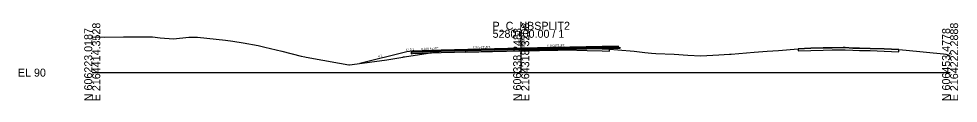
# Model space of a CAD drawing. Extents: x -26 to 1303, y -10 to 12038.
# Drawn here: x -25.7 to 302.8, y 490.3 to 517.8 of the extents above; entities that cross this region are included whole.
import ezdxf

# ---------------------------------------------------------------- set-up
doc = ezdxf.new("R2010")
doc.units = 0
for name, color, linetype in [('RD_GPK_XS_Cell', 7, 'Continuous'), ('RD_XS_Base', 7, 'Continuous'), ('RD_XS_ExGround', 7, 'Continuous'), ('RD_XS_ExPaveRet', 7, 'Continuous'), ('RD_XS_Greenside', 7, 'Continuous'), ('RD_XS_Pave', 7, 'Continuous'), ('RD_XS_PaveOvlay_CP', 7, 'Continuous'), ('RD_XS_TieSlope', 7, 'Continuous'), ('RD_XS_TX_Elev_EX', 7, 'Continuous'), ('RD_XS_TX_Elev_PR', 7, 'Continuous'), ('RD_XS_TX_ShdSlope', 7, 'Continuous'), ('RD_XS_TX_Slope', 7, 'Continuous')]:
    doc.layers.add(name, color=color, linetype=linetype)

msp = doc.modelspace()

# ---------------------------------------------------------------- linework, layer by layer
at = {"layer": 'RD_GPK_XS_Cell'}
for p, q in [((150, 500), (150, 515)), ((0, 500), (150, 500)), ((150, 500), (300, 500))]:
    msp.add_line(p, q, dxfattribs=at)
at = {"layer": 'RD_XS_Base'}
for p, q in [((112, 507.15), (111.5, 507.13)), ((111.5, 507.13), (111.5, 507.13)), ((111.5, 507.13), (111.5, 506.63)), ((111.5, 506.63), (112, 506.65)), ((122, 507.55), (112, 507.15)), ((112, 507.15), (112, 507.15)), ((112, 506.65), (122, 507.05)), ((112, 506.65), (112, 506.65)), ((150, 508.25), (122, 507.55)), ((122, 507.05), (150, 507.75)), ((122, 507.55), (122, 507.55)), ((122, 507.05), (122, 507.05)), ((150, 508.25), (184, 508.93)), ((184.5, 508.44), (150, 507.75)), ((150, 507.75), (150, 508.41)), ((150, 508.41), (150, 508.41)), ((150, 508.41), (150, 508.41)), ((150, 508.41), (150, 508.25)), ((150, 508.25), (150, 508.25)), ((150, 507.75), (150, 508.25)), ((150, 508.25), (150, 508.25)), ((150, 508.25), (150, 508.25)), ((150, 507.75), (150, 507.75)), ((174, 508.73), (174, 508.73)), ((174, 508.73), (174, 508.73)), ((174, 508.23), (174, 508.23)), ((174, 508.23), (174, 508.23)), ((184, 508.93), (184, 508.93)), ((184.5, 508.94), (184.5, 508.44)), ((184.5, 508.91), (184.5, 508.91))]:
    msp.add_line(p, q, dxfattribs=at)
at = {"layer": 'RD_XS_ExGround'}
msp.add_lwpolyline([(0, 512.4), (2.15, 512.52), (4.13, 512.42), (10.93, 512.5), (11.47, 512.49), (13.95, 512.5), (20.44, 512.53), (21.09, 512.53), (23.73, 512.19), (28.47, 511.89), (33.78, 512.45), (36.86, 512.46), (46.57, 511.31), (49.22, 510.96), (52.81, 510.38), (58.06, 509.52), (60.31, 508.95), (66.35, 507.5), (73.05, 505.81), (74.33, 505.49), (74.82, 505.39), (86.47, 503.34), (89.77, 502.77), (90.02, 502.7), (90.87, 502.83), (103.02, 504.5), (108.63, 505.44), (108.83, 505.48), (108.92, 505.5), (109.18, 505.54), (122.06, 507.51), (128.05, 507.78), (130.54, 507.86), (139.93, 508.13), (149.84, 508.42), (152.85, 508.44), (156.44, 508.5), (161.77, 508.58), (162.15, 508.59), (162.82, 508.6), (165.07, 508.79), (165.68, 508.78), (173.08, 508.52), (178.33, 508.37), (180.93, 508.26), (183.75, 508.02), (189.49, 507.5), (193.22, 507.09), (195.63, 506.8), (197.15, 506.75), (203.51, 506.5), (208.33, 506.15), (212.82, 505.83), (219.1, 506.23), (222.88, 506.5), (223.38, 506.5), (231.53, 507.17), (236.01, 507.5), (239.99, 507.78), (246.82, 508.37), (251.32, 508.54), (255.62, 508.63), (258.76, 508.71), (262.56, 508.77), (262.64, 508.79), (263.31, 508.75), (265.94, 508.62), (268.28, 508.55), (272.04, 508.5), (276.9, 508.28), (279.48, 508.18), (282.13, 508.05), (284.62, 507.87), (297.69, 506.53), (298.46, 506.41), (299.37, 506.25), (300, 506.12)], dxfattribs=at)
at = {"layer": 'RD_XS_ExPaveRet'}
for points in [[(180.93, 508.26), (178.33, 508.37), (178.33, 508.37), (173.08, 508.52), (173.08, 508.52), (165.68, 508.78), (165.68, 508.78), (165.07, 508.79), (165.07, 508.79), (165.07, 508.79), (162.82, 508.6), (162.82, 508.6), (162.15, 508.59), (161.77, 508.58), (156.44, 508.5), (156.44, 508.5), (156.44, 508.5), (152.85, 508.44), (152.85, 508.44), (149.84, 508.42), (139.93, 508.13), (139.93, 508.13), (130.54, 507.86), (130.54, 507.86), (130.54, 507.86), (130.54, 507.11), (130.54, 507.11), (139.93, 507.38), (139.93, 507.38), (149.84, 507.67), (152.85, 507.69), (152.85, 507.69), (156.44, 507.75), (156.44, 507.75), (156.44, 507.75), (161.77, 507.83), (162.15, 507.84), (162.82, 507.85), (162.82, 507.85), (165.07, 508.04), (165.07, 508.04), (165.07, 508.04), (165.68, 508.03), (165.68, 508.03), (173.08, 507.77), (173.08, 507.77), (178.33, 507.62), (178.33, 507.62), (180.93, 507.51), (180.93, 507.51), (180.93, 508.26), (180.93, 508.26), (180.93, 508.26)], [(180.93, 508.26), (178.33, 508.37), (173.08, 508.52), (165.68, 508.78), (165.07, 508.79), (162.82, 508.6), (162.15, 508.59), (161.77, 508.58), (156.44, 508.5), (152.85, 508.44), (149.84, 508.42), (139.93, 508.13), (130.54, 507.86), (130.54, 507.11), (139.93, 507.38), (149.84, 507.67), (152.85, 507.69), (156.44, 507.75), (161.77, 507.83), (162.15, 507.84), (162.82, 507.85), (165.07, 508.04), (165.68, 508.03), (173.08, 507.77), (178.33, 507.62), (180.93, 507.51), (180.93, 507.51), (180.93, 508.26), (180.93, 508.26)], [(279.48, 508.18), (276.9, 508.28), (276.9, 508.28), (272.04, 508.5), (272.04, 508.5), (268.28, 508.55), (268.28, 508.55), (265.94, 508.62), (265.94, 508.62), (265.94, 508.62), (263.31, 508.75), (262.64, 508.79), (262.64, 508.79), (262.56, 508.77), (262.56, 508.77), (258.76, 508.71), (258.76, 508.71), (258.76, 508.71), (255.62, 508.63), (255.62, 508.63), (251.32, 508.54), (251.32, 508.54), (246.82, 508.37), (246.82, 508.37), (246.82, 507.62), (251.32, 507.79), (251.32, 507.79), (255.62, 507.88), (255.62, 507.88), (258.76, 507.96), (258.76, 507.96), (258.76, 507.96), (262.56, 508.02), (262.56, 508.02), (262.64, 508.04), (262.64, 508.04), (263.31, 508), (265.94, 507.87), (265.94, 507.87), (265.94, 507.87), (268.28, 507.8), (268.28, 507.8), (272.04, 507.75), (272.04, 507.75), (276.9, 507.53), (276.9, 507.53), (279.48, 507.43), (279.48, 507.43), (282.13, 507.3), (282.13, 508.05), (282.13, 508.05), (279.48, 508.18), (279.48, 508.18)], [(279.48, 508.18), (276.9, 508.28), (272.04, 508.5), (268.28, 508.55), (265.94, 508.62), (263.31, 508.75), (262.64, 508.79), (262.56, 508.77), (258.76, 508.71), (255.62, 508.63), (251.32, 508.54), (246.82, 508.37), (246.82, 507.62), (251.32, 507.79), (255.62, 507.88), (258.76, 507.96), (262.56, 508.02), (262.64, 508.04), (263.31, 508), (265.94, 507.87), (268.28, 507.8), (272.04, 507.75), (276.9, 507.53), (279.48, 507.43), (282.13, 507.3), (282.13, 508.05), (279.48, 508.18)]]:
    msp.add_lwpolyline(points, dxfattribs=at)
at = {"layer": 'RD_XS_Greenside'}
msp.add_line((110, 507.3), (93.59, 503.2), dxfattribs=at)
at = {"layer": 'RD_XS_Pave'}
for p, q in [((184, 509.24), (150, 508.56)), ((184, 509.09), (184, 509.24)), ((184, 509.24), (184, 509.24)), ((122, 507.86), (112, 507.46)), ((122, 507.71), (112, 507.31)), ((112, 507.31), (122, 507.71)), ((112, 507.15), (122, 507.55)), ((112, 507.46), (112, 507.46)), ((112, 507.46), (112, 507.31)), ((112, 507.31), (112, 507.31)), ((112, 507.31), (112, 507.15)), ((150, 508.56), (122, 507.86)), ((150, 508.41), (122, 507.71)), ((122, 507.71), (150, 508.41)), ((122, 507.55), (150, 508.25)), ((122, 507.86), (122, 507.86)), ((122, 507.71), (122, 507.71)), ((122, 507.71), (122, 507.71)), ((122, 507.55), (122, 507.55)), ((184, 509.09), (150, 508.41)), ((150, 508.41), (184, 509.09)), ((150, 508.25), (184.5, 508.94)), ((150, 508.56), (150, 508.56)), ((150, 508.25), (150, 508.41)), ((150, 508.41), (150, 508.41)), ((150, 508.41), (150, 508.41)), ((150, 508.41), (150, 508.41)), ((150, 508.41), (150, 508.41)), ((150, 508.41), (150, 508.25)), ((150, 508.41), (150, 508.41)), ((150, 508.25), (150, 508.25)), ((150, 508.25), (150, 508.25)), ((174, 509.04), (174, 509.04)), ((174, 509.04), (174, 509.04)), ((174, 508.89), (174, 508.89)), ((174, 508.89), (174, 508.89)), ((174, 508.89), (174, 508.89)), ((174, 508.89), (174, 508.89)), ((174, 508.73), (174, 508.73)), ((174, 508.73), (174, 508.73)), ((184, 508.93), (184, 509.09)), ((184, 509.09), (184, 509.09))]:
    msp.add_line(p, q, dxfattribs=at)
at = {"layer": 'RD_XS_PaveOvlay_CP'}
for p, q in [((184, 509.24), (150, 508.56)), ((122, 507.86), (112, 507.46)), ((150, 508.56), (122, 507.86)), ((122, 507.86), (122, 507.86)), ((150, 508.56), (150, 508.56)), ((174, 509.04), (174, 509.04)), ((174, 509.04), (174, 509.04))]:
    msp.add_line(p, q, dxfattribs=at)
at = {"layer": 'RD_XS_TieSlope'}
msp.add_line((112, 507.46), (110, 507.3), dxfattribs=at)

# ---------------------------------------------------------------- texts
at = {"layer": 'RD_GPK_XS_Cell'}
for s, p in [('E 2164414.3528', (2.8, 490)), ('E 2164318.3208', (152.8, 490)), ('E 2164222.2888', (302.8, 490)), ('N 606223.0187', (0, 490)), ('N 606338.2483', (150, 490)), ('N 606453.4778', (300, 490))]:
    msp.add_text(s, height=2.8, rotation=90, dxfattribs=at).set_placement(p)
for s, p in [('P_C_NBSPLIT2', (140, 515)), ('5280+00.00 / 1', (140, 512.2)), ('EL 90', (-26, 498.6))]:
    msp.add_text(s, height=2.8, dxfattribs=at).set_placement(p)
at = {"layer": 'RD_XS_TX_Elev_EX'}
msp.add_text('98.42', height=0.6, rotation=90, dxfattribs=at).set_placement((149.67, 509.31))
at = {"layer": 'RD_XS_TX_Elev_PR'}
msp.add_text('98.56', height=1, rotation=90, dxfattribs=at).set_placement((151.24, 508.99))
at = {"layer": 'RD_XS_TX_ShdSlope'}
msp.add_text('12.5:1', height=0.75, rotation=4.5739, dxfattribs=at).set_placement((109.66, 507.59))
at = {"layer": 'RD_XS_TX_Slope'}
for s, rotation, p in [('0.025 FT./FT.', 1.4321, (133.14, 508.44)), ('0.020 FT./FT.', 1.1458, (159.15, 509.05)), ('4:1', 14.0362, (100.06, 505.3)), ('0.040 FT./FT.', 2.2906, (115.14, 507.89))]:
    msp.add_text(s, height=0.75, rotation=rotation, dxfattribs=at).set_placement(p)

doc.saveas('drawing.dxf')
